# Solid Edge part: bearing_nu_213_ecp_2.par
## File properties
Title: Cylindrical roller bearings, single row, axial displacement in both directions, NU design, Bore Ø 65 mm, Outside Ø 120 mm
Author: TraceParts S.A.
Template: Iso Metric Part.par
Last saved by: Nimesh.N
Revision: 11
Application: TraceParts
Company: TraceParts S.A.
Density: 7800.000 kg/m^3
Accuracy: 0.990
REFERENCE: NU 213 ECP
SUPPLIER: SKF
DESIGN: Cylindrical roller bearings, single row, axial displacement in both directions, NU design, Bore Ø 65 mm, Outside Ø 120 mm
MASS: 1.013
TraceParts.PartNumber: 10-20012017-072320
TraceParts.PartTitle: Cylindrical roller bearings, single row, axial displacement in both directions, NU design, Bore Ø 65 mm, Outside Ø 120 mm
TraceParts.InstanceId: 10-20012017-0723206W19M4V3IEJX75N7S7B5ETKO
TraceParts.PartVersion: 1.1.5
TraceParts.PartLanguage: en
Username: Nimesh.N
Material: Steel - Alloyed:1.7016 , 17Cr3
Face Style: Steel
Fill Style: ANSI32(Steel)
Grouping: Steel\Steel - Alloyed (Cr)
LibraryName: Materials-DIN
Coef. of Thermal Exp: 1.1e-05
Thermal Conductivity: 14.0
Specific Heat: 440.0
Modulus of Elasticity: 210000003072.0
Poisson's Ratio: 0.28
Yield Stress: 420000000.0
Ultimate Stress: 550000000.0
Elongation: 0.0
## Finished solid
Body 1: solid body, 96 faces, 96 edges, 96 vertices.
  Faces by surface: torus 48, plane 32, cylinder 16
  Edges by curve: circle 64, spline 32
Body 2: solid body, 10 faces, 10 edges, 10 vertices.
  Faces by surface: torus 4, cone 2, cylinder 2, plane 2
  Edges by curve: circle 10
Body 3: solid body, 12 faces, 12 edges, 12 vertices.
  Faces by surface: cylinder 4, plane 4, torus 4
  Edges by curve: circle 12
Bounding box of the edges (mm; curved faces can reach further): 23.000 x 120.000 x 120.000, from (0, -60, -60) to (23, 60, 60).
Cylindrical faces by radius (mm): R7.5 x16, R32.5 x1, R39.25 x1, R51.6 x2, R54.25 x1, R60 x1
Conical faces (half-angle, radius in mm at the cone's reference point): 15 deg R38.7439 x2
Toroidal faces (ring radius, tube radius in mm): R7.2 r0.3 x32, R34 r1.5 x2, R37.948 r0.3 x2, R46.75 r0.015 x16, R51.9 r0.3 x2, R58.5 r1.5 x2
Planar faces by outward normal: +x 19, -x 19
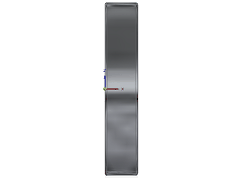
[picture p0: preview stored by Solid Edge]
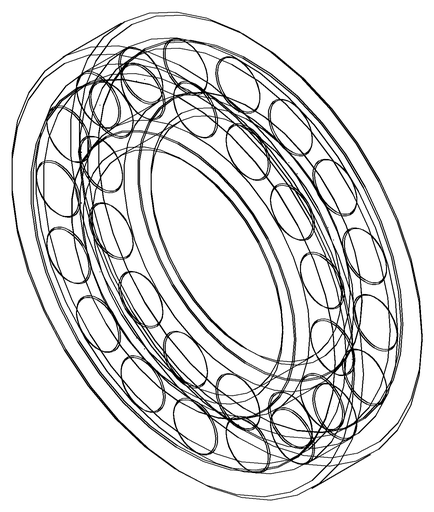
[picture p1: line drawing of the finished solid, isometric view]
